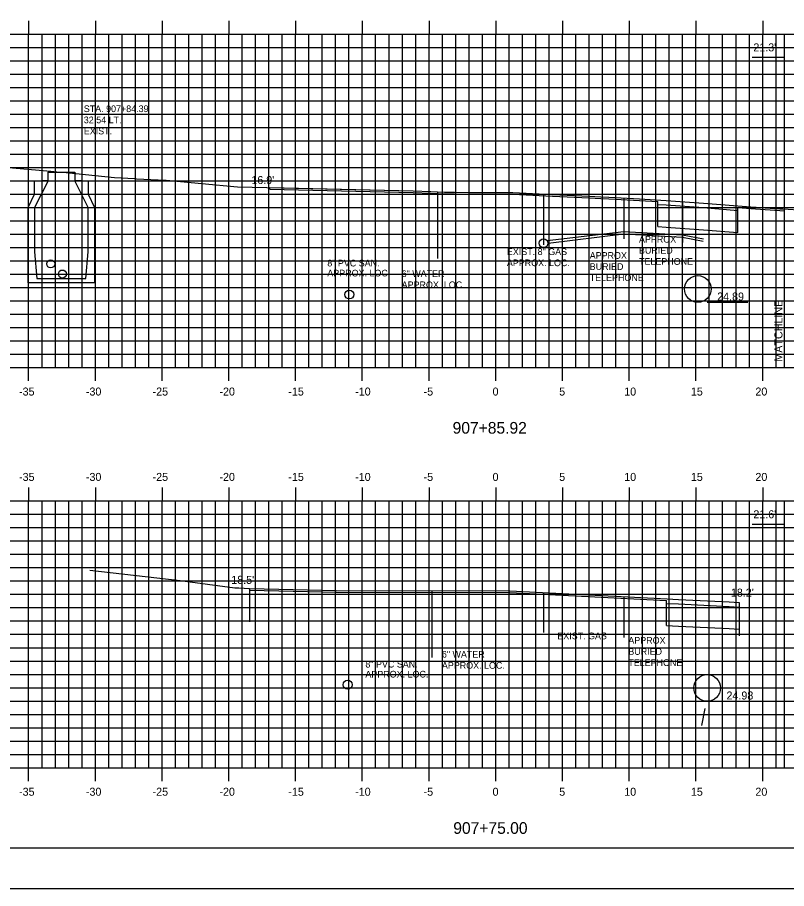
# Model space of a CAD drawing. Extents: x 1026131 to 1026301, y 394697 to 394807.
# Drawn here: x 1026178.5 to 1026236.1, y 394696.5 to 394761.9 of the extents above; entities that cross this region are included whole.
import ezdxf

# ---------------------------------------------------------------- set-up
doc = ezdxf.new("R2010")
doc.units = 0
for name, color, linetype in [('ANNOTATION', 7, 'Continuous'), ('BORDER', 7, 'Continuous'), ('D_Drainage_Culvert', 7, 'Continuous'), ('D_Drainage_Text', 7, 'Continuous'), ('D_Roadway_FinishedGrade', 7, 'Continuous'), ('D_Text_Monospaced', 7, 'Continuous'), ('D_Text_Standard', 7, 'Continuous'), ('H_V ANNOTATION', 7, 'Continuous'), ('MAJOR', 7, 'Continuous'), ('MINOR', 7, 'Continuous'), ('PLOT BOUNDARY', 7, 'Continuous'), ('S_Drainage_CB', 7, 'Continuous'), ('S_Drainage_Invert', 7, 'Continuous'), ('S_Roadway_Centerline', 7, 'Continuous'), ('S_Roadway_Edge_Pavement', 7, 'Continuous'), ('S_Utilities_UG_Gas_Line', 7, 'Continuous'), ('S_Utilities_UG_Sanitary_Sewer', 7, 'Continuous'), ('S_Utilities_UG_Water_Line', 7, 'Continuous')]:
    doc.layers.add(name, color=color, linetype=linetype)

msp = doc.modelspace()

# ---------------------------------------------------------------- linework, layer by layer
at = {"layer": 'ANNOTATION'}
for p, q in [((1026233.564, 394758.868), (1026235.983, 394758.868)), ((1026233.564, 394723.868), (1026235.983, 394723.868)), ((1026229.772, 394708.778), (1026230.039, 394710.054))]:
    msp.add_line(p, q, dxfattribs=at)
at = {"layer": 'BORDER'}
msp.add_line((1026139.345, 394699.607), (1026299.345, 394699.607), dxfattribs=at)
at = {"layer": 'D_Drainage_Culvert'}
for centre in [(1026229.484, 394741.497), (1026230.183, 394711.587)]:
    msp.add_circle(centre, 1, dxfattribs=at)
at = {"layer": 'D_Drainage_Text'}
for points in [[(1026230.179, 394740.519), (1026231.398, 394740.519), (1026233.239, 394740.519)], [(1026230.878, 394710.609), (1026232.097, 394710.609), (1026233.938, 394710.609)]]:
    msp.add_lwpolyline(points, dxfattribs=at)
at = {"layer": 'D_Roadway_FinishedGrade'}
for p, q in [((1026235.983, 394735.607), (1026235.983, 394760.607)), ((1026197.426, 394748.977), (1026197.426, 394749.102)), ((1026226.478, 394746.172), (1026226.478, 394748.047)), ((1026232.478, 394745.725), (1026232.478, 394747.6)), ((1026235.983, 394705.607), (1026235.983, 394725.607)), ((1026227.127, 394716.263), (1026227.127, 394718.139))]:
    msp.add_line(p, q, dxfattribs=at)
for points in [[(1026197.426, 394749.102), (1026207.079, 394748.878), (1026208.153, 394748.844), (1026209.473, 394748.801), (1026210.495, 394748.766), (1026211.246, 394748.752), (1026212.328, 394748.73), (1026215.619, 394748.72), (1026218.593, 394748.568), (1026221.339, 394748.457), (1026222.225, 394748.413), (1026222.825, 394748.372), (1026223.744, 394748.317), (1026225.118, 394748.242), (1026227.118, 394748.139), (1026229.902, 394747.925), (1026233.45, 394747.649), (1026235.983, 394747.488)], [(1026197.426, 394748.977), (1026207.079, 394748.753), (1026208.153, 394748.719), (1026209.473, 394748.676), (1026210.495, 394748.641), (1026211.246, 394748.627), (1026212.328, 394748.605), (1026215.619, 394748.595), (1026218.593, 394748.443), (1026221.339, 394748.332), (1026222.225, 394748.288), (1026222.825, 394748.247), (1026223.744, 394748.192), (1026225.118, 394748.117), (1026226.478, 394748.047)], [(1026226.478, 394747.839), (1026227.118, 394747.806), (1026229.902, 394747.592), (1026232.478, 394747.391)], [(1026232.478, 394747.6), (1026233.45, 394747.524), (1026235.983, 394747.363)], [(1026226.478, 394746.172), (1026227.118, 394746.139), (1026229.902, 394745.925), (1026232.478, 394745.725)], [(1026195.894, 394719.033), (1026198.093, 394718.991), (1026202.376, 394718.903), (1026215.403, 394718.862), (1026227.174, 394718.261), (1026228.046, 394718.226), (1026231.842, 394718.037), (1026232.572, 394717.988)], [(1026195.894, 394718.908), (1026198.093, 394718.866), (1026202.376, 394718.778), (1026215.403, 394718.737), (1026227.127, 394718.139)], [(1026227.127, 394717.93), (1026228.046, 394717.893), (1026231.842, 394717.704), (1026232.572, 394717.655)], [(1026227.127, 394716.263), (1026228.046, 394716.226), (1026231.842, 394716.037), (1026232.572, 394715.988)]]:
    msp.add_lwpolyline(points, dxfattribs=at)
at = {"layer": 'MAJOR'}
for p, q in [((1026179.344, 394761.609), (1026179.344, 394760.607)), ((1026184.344, 394761.609), (1026184.344, 394760.607)), ((1026189.344, 394761.609), (1026189.344, 394760.607)), ((1026194.344, 394761.609), (1026194.344, 394760.607)), ((1026199.344, 394761.609), (1026199.344, 394760.607)), ((1026204.344, 394761.609), (1026204.344, 394760.607)), ((1026209.344, 394761.609), (1026209.344, 394760.607)), ((1026214.344, 394761.609), (1026214.344, 394760.607)), ((1026219.344, 394761.609), (1026219.344, 394760.607)), ((1026224.344, 394761.609), (1026224.344, 394760.607)), ((1026229.344, 394761.609), (1026229.344, 394760.607)), ((1026234.344, 394761.609), (1026234.344, 394760.607)), ((1026144.344, 394760.607), (1026284.344, 394760.607)), ((1026179.344, 394735.607), (1026179.344, 394760.607)), ((1026184.344, 394735.607), (1026184.344, 394760.607)), ((1026189.344, 394735.607), (1026189.344, 394760.607)), ((1026194.344, 394735.607), (1026194.344, 394760.607)), ((1026199.344, 394735.607), (1026199.344, 394760.607)), ((1026204.344, 394735.607), (1026204.344, 394760.607)), ((1026209.344, 394735.607), (1026209.344, 394760.607)), ((1026214.344, 394735.607), (1026214.344, 394760.607)), ((1026219.344, 394735.607), (1026219.344, 394760.607)), ((1026224.344, 394735.607), (1026224.344, 394760.607)), ((1026229.344, 394735.607), (1026229.344, 394760.607)), ((1026234.344, 394735.607), (1026234.344, 394760.607)), ((1026144.344, 394755.607), (1026284.344, 394755.607)), ((1026144.344, 394750.607), (1026284.344, 394750.607)), ((1026144.344, 394745.607), (1026284.344, 394745.607)), ((1026144.344, 394740.607), (1026284.344, 394740.607)), ((1026144.344, 394735.607), (1026284.344, 394735.607)), ((1026179.344, 394734.605), (1026179.344, 394735.607)), ((1026184.344, 394734.605), (1026184.344, 394735.607)), ((1026189.344, 394734.605), (1026189.344, 394735.607)), ((1026194.344, 394734.605), (1026194.344, 394735.607)), ((1026199.344, 394734.605), (1026199.344, 394735.607)), ((1026204.344, 394734.605), (1026204.344, 394735.607)), ((1026209.344, 394734.605), (1026209.344, 394735.607)), ((1026214.344, 394734.605), (1026214.344, 394735.607)), ((1026219.344, 394734.605), (1026219.344, 394735.607)), ((1026224.344, 394734.605), (1026224.344, 394735.607)), ((1026229.344, 394734.605), (1026229.344, 394735.607)), ((1026234.344, 394734.605), (1026234.344, 394735.607)), ((1026179.344, 394726.609), (1026179.344, 394725.607)), ((1026184.344, 394726.609), (1026184.344, 394725.607)), ((1026189.344, 394726.609), (1026189.344, 394725.607)), ((1026194.344, 394726.609), (1026194.344, 394725.607)), ((1026199.344, 394726.609), (1026199.344, 394725.607)), ((1026204.344, 394726.609), (1026204.344, 394725.607)), ((1026209.344, 394726.609), (1026209.344, 394725.607)), ((1026214.344, 394726.609), (1026214.344, 394725.607)), ((1026219.344, 394726.609), (1026219.344, 394725.607)), ((1026224.344, 394726.609), (1026224.344, 394725.607)), ((1026229.344, 394726.609), (1026229.344, 394725.607)), ((1026234.344, 394726.609), (1026234.344, 394725.607)), ((1026144.344, 394725.607), (1026284.344, 394725.607)), ((1026179.344, 394705.607), (1026179.344, 394725.607)), ((1026184.344, 394705.607), (1026184.344, 394725.607)), ((1026189.344, 394705.607), (1026189.344, 394725.607)), ((1026194.344, 394705.607), (1026194.344, 394725.607)), ((1026199.344, 394705.607), (1026199.344, 394725.607)), ((1026204.344, 394705.607), (1026204.344, 394725.607)), ((1026209.344, 394705.607), (1026209.344, 394725.607)), ((1026214.344, 394705.607), (1026214.344, 394725.607)), ((1026219.344, 394705.607), (1026219.344, 394725.607)), ((1026224.344, 394705.607), (1026224.344, 394725.607)), ((1026229.344, 394705.607), (1026229.344, 394725.607)), ((1026234.344, 394705.607), (1026234.344, 394725.607)), ((1026144.344, 394720.607), (1026284.344, 394720.607)), ((1026144.344, 394715.607), (1026284.344, 394715.607)), ((1026144.344, 394710.607), (1026284.344, 394710.607)), ((1026144.344, 394705.607), (1026284.344, 394705.607)), ((1026179.344, 394704.605), (1026179.344, 394705.607)), ((1026184.344, 394704.605), (1026184.344, 394705.607)), ((1026189.344, 394704.605), (1026189.344, 394705.607)), ((1026194.344, 394704.605), (1026194.344, 394705.607)), ((1026199.344, 394704.605), (1026199.344, 394705.607)), ((1026204.344, 394704.605), (1026204.344, 394705.607)), ((1026209.344, 394704.605), (1026209.344, 394705.607)), ((1026214.344, 394704.605), (1026214.344, 394705.607)), ((1026219.344, 394704.605), (1026219.344, 394705.607)), ((1026224.344, 394704.605), (1026224.344, 394705.607)), ((1026229.344, 394704.605), (1026229.344, 394705.607)), ((1026234.344, 394704.605), (1026234.344, 394705.607))]:
    msp.add_line(p, q, dxfattribs=at)
at = {"layer": 'MINOR'}
for p, q in [((1026180.344, 394735.607), (1026180.344, 394760.607)), ((1026181.344, 394735.607), (1026181.344, 394760.607)), ((1026182.344, 394735.607), (1026182.344, 394760.607)), ((1026183.344, 394735.607), (1026183.344, 394760.607)), ((1026185.344, 394735.607), (1026185.344, 394760.607)), ((1026186.344, 394735.607), (1026186.344, 394760.607)), ((1026187.344, 394735.607), (1026187.344, 394760.607)), ((1026188.344, 394735.607), (1026188.344, 394760.607)), ((1026190.344, 394735.607), (1026190.344, 394760.607)), ((1026191.344, 394735.607), (1026191.344, 394760.607)), ((1026192.344, 394735.607), (1026192.344, 394760.607)), ((1026193.344, 394735.607), (1026193.344, 394760.607)), ((1026195.344, 394735.607), (1026195.344, 394760.607)), ((1026196.344, 394735.607), (1026196.344, 394760.607)), ((1026197.344, 394735.607), (1026197.344, 394760.607)), ((1026198.344, 394735.607), (1026198.344, 394760.607)), ((1026200.344, 394735.607), (1026200.344, 394760.607)), ((1026201.344, 394735.607), (1026201.344, 394760.607)), ((1026202.344, 394735.607), (1026202.344, 394760.607)), ((1026203.344, 394735.607), (1026203.344, 394760.607)), ((1026205.344, 394735.607), (1026205.344, 394760.607)), ((1026206.344, 394735.607), (1026206.344, 394760.607)), ((1026207.344, 394735.607), (1026207.344, 394760.607)), ((1026208.344, 394735.607), (1026208.344, 394760.607)), ((1026210.344, 394735.607), (1026210.344, 394760.607)), ((1026211.344, 394735.607), (1026211.344, 394760.607)), ((1026212.344, 394735.607), (1026212.344, 394760.607)), ((1026213.344, 394735.607), (1026213.344, 394760.607)), ((1026215.344, 394735.607), (1026215.344, 394760.607)), ((1026216.344, 394735.607), (1026216.344, 394760.607)), ((1026217.344, 394735.607), (1026217.344, 394760.607)), ((1026218.344, 394735.607), (1026218.344, 394760.607)), ((1026220.344, 394735.607), (1026220.344, 394760.607)), ((1026221.344, 394735.607), (1026221.344, 394760.607)), ((1026222.344, 394735.607), (1026222.344, 394760.607)), ((1026223.344, 394735.607), (1026223.344, 394760.607)), ((1026225.344, 394735.607), (1026225.344, 394760.607)), ((1026226.344, 394735.607), (1026226.344, 394760.607)), ((1026227.344, 394735.607), (1026227.344, 394760.607)), ((1026228.344, 394735.607), (1026228.344, 394760.607)), ((1026230.344, 394735.607), (1026230.344, 394760.607)), ((1026231.344, 394735.607), (1026231.344, 394760.607)), ((1026232.344, 394735.607), (1026232.344, 394760.607)), ((1026233.344, 394735.607), (1026233.344, 394760.607)), ((1026235.344, 394735.607), (1026235.344, 394760.607)), ((1026144.344, 394759.607), (1026284.344, 394759.607)), ((1026144.344, 394758.607), (1026284.344, 394758.607)), ((1026144.344, 394757.607), (1026284.344, 394757.607)), ((1026144.344, 394756.607), (1026284.344, 394756.607)), ((1026144.344, 394754.607), (1026284.344, 394754.607)), ((1026144.344, 394753.607), (1026284.344, 394753.607)), ((1026144.344, 394752.607), (1026284.344, 394752.607)), ((1026144.344, 394751.607), (1026284.344, 394751.607)), ((1026144.344, 394749.607), (1026284.344, 394749.607)), ((1026144.344, 394748.607), (1026284.344, 394748.607)), ((1026144.344, 394747.607), (1026284.344, 394747.607)), ((1026144.344, 394746.607), (1026284.344, 394746.607)), ((1026144.344, 394744.607), (1026284.344, 394744.607)), ((1026144.344, 394743.607), (1026284.344, 394743.607)), ((1026144.344, 394742.607), (1026284.344, 394742.607)), ((1026144.344, 394741.607), (1026284.344, 394741.607)), ((1026144.344, 394739.607), (1026284.344, 394739.607)), ((1026144.344, 394738.607), (1026284.344, 394738.607)), ((1026144.344, 394737.607), (1026284.344, 394737.607)), ((1026144.344, 394736.607), (1026284.344, 394736.607)), ((1026180.344, 394705.607), (1026180.344, 394725.607)), ((1026181.344, 394705.607), (1026181.344, 394725.607)), ((1026182.344, 394705.607), (1026182.344, 394725.607)), ((1026183.344, 394705.607), (1026183.344, 394725.607)), ((1026185.344, 394705.607), (1026185.344, 394725.607)), ((1026186.344, 394705.607), (1026186.344, 394725.607)), ((1026187.344, 394705.607), (1026187.344, 394725.607)), ((1026188.344, 394705.607), (1026188.344, 394725.607)), ((1026190.344, 394705.607), (1026190.344, 394725.607)), ((1026191.344, 394705.607), (1026191.344, 394725.607)), ((1026192.344, 394705.607), (1026192.344, 394725.607)), ((1026193.344, 394705.607), (1026193.344, 394725.607)), ((1026195.344, 394705.607), (1026195.344, 394725.607)), ((1026196.344, 394705.607), (1026196.344, 394725.607)), ((1026197.344, 394705.607), (1026197.344, 394725.607)), ((1026198.344, 394705.607), (1026198.344, 394725.607)), ((1026200.344, 394705.607), (1026200.344, 394725.607)), ((1026201.344, 394705.607), (1026201.344, 394725.607)), ((1026202.344, 394705.607), (1026202.344, 394725.607)), ((1026203.344, 394705.607), (1026203.344, 394725.607)), ((1026205.344, 394705.607), (1026205.344, 394725.607)), ((1026206.344, 394705.607), (1026206.344, 394725.607)), ((1026207.344, 394705.607), (1026207.344, 394725.607)), ((1026208.344, 394705.607), (1026208.344, 394725.607)), ((1026210.344, 394705.607), (1026210.344, 394725.607)), ((1026211.344, 394705.607), (1026211.344, 394725.607)), ((1026212.344, 394705.607), (1026212.344, 394725.607)), ((1026213.344, 394705.607), (1026213.344, 394725.607)), ((1026215.344, 394705.607), (1026215.344, 394725.607)), ((1026216.344, 394705.607), (1026216.344, 394725.607)), ((1026217.344, 394705.607), (1026217.344, 394725.607)), ((1026218.344, 394705.607), (1026218.344, 394725.607)), ((1026220.344, 394705.607), (1026220.344, 394725.607)), ((1026221.344, 394705.607), (1026221.344, 394725.607)), ((1026222.344, 394705.607), (1026222.344, 394725.607)), ((1026223.344, 394705.607), (1026223.344, 394725.607)), ((1026225.344, 394705.607), (1026225.344, 394725.607)), ((1026226.344, 394705.607), (1026226.344, 394725.607)), ((1026227.344, 394705.607), (1026227.344, 394725.607)), ((1026228.344, 394705.607), (1026228.344, 394725.607)), ((1026230.344, 394705.607), (1026230.344, 394725.607)), ((1026231.344, 394705.607), (1026231.344, 394725.607)), ((1026232.344, 394705.607), (1026232.344, 394725.607)), ((1026233.344, 394705.607), (1026233.344, 394725.607)), ((1026235.344, 394705.607), (1026235.344, 394725.607)), ((1026144.344, 394724.607), (1026284.344, 394724.607)), ((1026144.344, 394723.607), (1026284.344, 394723.607)), ((1026144.344, 394722.607), (1026284.344, 394722.607)), ((1026144.344, 394721.607), (1026284.344, 394721.607)), ((1026144.344, 394719.607), (1026284.344, 394719.607)), ((1026144.344, 394718.607), (1026284.344, 394718.607)), ((1026144.344, 394717.607), (1026284.344, 394717.607)), ((1026144.344, 394716.607), (1026284.344, 394716.607)), ((1026144.344, 394714.607), (1026284.344, 394714.607)), ((1026144.344, 394713.607), (1026284.344, 394713.607)), ((1026144.344, 394712.607), (1026284.344, 394712.607)), ((1026144.344, 394711.607), (1026284.344, 394711.607)), ((1026144.344, 394709.607), (1026284.344, 394709.607)), ((1026144.344, 394708.607), (1026284.344, 394708.607)), ((1026144.344, 394707.607), (1026284.344, 394707.607)), ((1026144.344, 394706.607), (1026284.344, 394706.607))]:
    msp.add_line(p, q, dxfattribs=at)
at = {"layer": 'PLOT BOUNDARY'}
msp.add_lwpolyline([(1026131.251, 394696.548), (1026301.251, 394696.548), (1026301.251, 394806.548), (1026131.251, 394806.548)], close=True, dxfattribs=at)
at = {"layer": 'S_Drainage_CB'}
for p, q in [((1026179.791, 394748.609), (1026179.791, 394749.593)), ((1026179.791, 394749.593), (1026180.808, 394749.593)), ((1026180.808, 394749.593), (1026179.791, 394747.592)), ((1026182.809, 394749.593), (1026183.794, 394749.593)), ((1026183.794, 394747.592), (1026182.809, 394749.593)), ((1026183.794, 394749.593), (1026183.794, 394748.609)), ((1026179.299, 394747.592), (1026179.791, 394748.609)), ((1026183.794, 394748.609), (1026184.286, 394747.592)), ((1026179.299, 394741.949), (1026179.299, 394747.592)), ((1026179.791, 394747.592), (1026179.791, 394744.278)), ((1026183.794, 394744.278), (1026183.794, 394747.592)), ((1026184.286, 394747.592), (1026184.286, 394741.949)), ((1026179.791, 394744.278), (1026179.955, 394742.277)), ((1026183.63, 394742.277), (1026183.794, 394744.278)), ((1026179.955, 394742.277), (1026183.63, 394742.277)), ((1026184.286, 394741.949), (1026179.299, 394741.949))]:
    msp.add_line(p, q, dxfattribs=at)
msp.add_lwpolyline([(1026180.316, 394749.635), (1026180.808, 394749.635), (1026180.808, 394750.258), (1026182.809, 394750.258), (1026182.809, 394749.635), (1026183.301, 394749.635)], dxfattribs=at)
at = {"layer": 'S_Drainage_Invert'}
for centre in [(1026180.996, 394743.38), (1026181.872, 394742.619)]:
    msp.add_circle(centre, 0.3, dxfattribs=at)
at = {"layer": 'S_Roadway_Centerline'}
for points in [[(1026164.577, 394751.744), (1026181.002, 394750.326), (1026181.69, 394750.257), (1026182.149, 394750.228), (1026182.162, 394750.227), (1026185.786, 394749.86), (1026187.271, 394749.767), (1026187.434, 394749.754), (1026189.053, 394749.679), (1026189.652, 394749.641), (1026194.984, 394749.158), (1026207.079, 394748.878), (1026208.153, 394748.844), (1026209.473, 394748.801), (1026210.495, 394748.766), (1026211.246, 394748.752), (1026212.328, 394748.73), (1026215.619, 394748.72), (1026218.593, 394748.568), (1026221.339, 394748.457), (1026222.225, 394748.413), (1026222.825, 394748.372), (1026223.744, 394748.317), (1026225.118, 394748.242), (1026227.118, 394748.139), (1026229.902, 394747.925), (1026233.45, 394747.649), (1026239.83, 394747.244)], [(1026183.923, 394720.429), (1026190.689, 394719.645), (1026194.804, 394719.102), (1026195.091, 394719.09), (1026195.48, 394719.069), (1026195.846, 394719.033), (1026195.894, 394719.033), (1026198.093, 394718.991), (1026202.376, 394718.903), (1026215.403, 394718.862), (1026227.174, 394718.261), (1026228.046, 394718.226), (1026231.842, 394718.037), (1026232.572, 394717.988)]]:
    msp.add_lwpolyline(points, dxfattribs=at)
at = {"layer": 'S_Roadway_Edge_Pavement'}
for p, q in [((1026195.894, 394719.033), (1026195.894, 394716.533)), ((1026232.572, 394717.988), (1026232.572, 394715.488))]:
    msp.add_line(p, q, dxfattribs=at)
at = {"layer": 'S_Utilities_UG_Gas_Line'}
for p, q in [((1026217.925, 394748.602), (1026217.925, 394745.602)), ((1026217.925, 394745.607), (1026217.925, 394744.801)), ((1026217.914, 394718.734), (1026217.914, 394715.734))]:
    msp.add_line(p, q, dxfattribs=at)
for points in [[(1026218.197, 394745.121), (1026223.944, 394745.8), (1026228.344, 394745.545), (1026229.908, 394745.247)], [(1026218.258, 394744.928), (1026223.947, 394745.633), (1026228.324, 394745.379), (1026229.876, 394745.083)]]:
    msp.add_lwpolyline(points, dxfattribs=at)
msp.add_circle((1026217.925, 394744.928), 0.333, dxfattribs=at)
at = {"layer": 'S_Utilities_UG_Sanitary_Sewer'}
for centre in [(1026203.367, 394741.08), (1026203.245, 394711.83)]:
    msp.add_circle(centre, 0.333, dxfattribs=at)
at = {"layer": 'S_Utilities_UG_Water_Line'}
for p, q in [((1026209.98, 394748.784), (1026209.98, 394743.784)), ((1026223.944, 394748.306), (1026223.944, 394745.253)), ((1026228.344, 394748.045), (1026228.344, 394744.992)), ((1026209.56, 394718.88), (1026209.56, 394713.88)), ((1026223.944, 394718.426), (1026223.944, 394715.373))]:
    msp.add_line(p, q, dxfattribs=at)

# ---------------------------------------------------------------- texts
at = {"layer": 'ANNOTATION'}
for s, p in [("21.3'", (1026233.644, 394759.307)), ("21.6'", (1026233.644, 394724.307))]:
    msp.add_text(s, height=0.6, dxfattribs=at).set_placement(p)
msp.add_text('MATCHLINE', height=0.6, rotation=90, dxfattribs=at).set_placement((1026235.824, 394736.048))
at = {"layer": 'D_Drainage_Text'}
for s, p in [('24.89', (1026230.933, 394740.632)), ('24.98', (1026231.632, 394710.722))]:
    msp.add_text(s, height=0.6, dxfattribs=at).set_placement(p)
at = {"layer": 'D_Text_Monospaced'}
for s, height, p in [('STA. 907+84.39', 0.49998, (1026183.475, 394754.756)), ('32.54 LT.', 0.5, (1026183.475, 394753.922)), ('EXIST. ', 0.5, (1026183.475, 394753.082)), ('APPROX', 0.5, (1026225.075, 394744.973)), ('EXIST. 8" GAS', 0.49998, (1026215.176, 394744.04)), ('APPROX', 0.5, (1026221.382, 394743.758)), ('BURIED ', 0.5, (1026225.075, 394744.14)), ('8" PVC SAN.', 0.49998, (1026201.722, 394743.186)), ('APPROX. LOC.', 0.49998, (1026215.176, 394743.207)), ('BURIED ', 0.5, (1026221.382, 394742.925)), ('TELEPHONE', 0.5, (1026225.075, 394743.307)), ('APPROX. LOC.', 0.49998, (1026201.722, 394742.436)), ('6" WATER', 0.5, (1026207.292, 394742.393)), ('TELEPHONE', 0.5, (1026221.382, 394742.091)), ('APPROX. LOC.', 0.49998, (1026207.292, 394741.56)), ('EXIST. GAS', 0.5, (1026218.954, 394715.239)), ('APPROX', 0.5, (1026224.276, 394714.905)), ('6" WATER', 0.5, (1026210.308, 394713.86)), ('BURIED ', 0.5, (1026224.276, 394714.072)), ('8" PVC SAN.', 0.49998, (1026204.574, 394713.12)), ('APPROX. LOC.', 0.49998, (1026210.308, 394713.027)), ('TELEPHONE', 0.5, (1026224.276, 394713.239)), ('APPROX. LOC.', 0.49998, (1026204.574, 394712.37))]:
    msp.add_text(s, height=height, dxfattribs=at).set_placement(p)
at = {"layer": 'D_Text_Standard'}
for s, p in [("-16.9'", (1026195.764, 394749.362)), ("-18.5'", (1026194.258, 394719.392)), ("18.2'", (1026231.962, 394718.434))]:
    msp.add_text(s, height=0.6, dxfattribs=at).set_placement(p)
at = {"layer": 'H_V ANNOTATION'}
for s, height, p in [('-35', 0.6, (1026178.624, 394733.507)), ('-30', 0.6, (1026183.632, 394733.507)), ('-25', 0.6, (1026188.63, 394733.507)), ('-20', 0.6, (1026193.638, 394733.507)), ('-15', 0.6, (1026198.801, 394733.507)), ('-10', 0.6, (1026203.809, 394733.507)), ('-5', 0.6, (1026208.935, 394733.507)), ('0', 0.6, (1026214.103, 394733.507)), ('5', 0.6, (1026219.095, 394733.507)), ('10', 0.6, (1026223.97, 394733.507)), ('15', 0.6, (1026228.962, 394733.507)), ('20', 0.6, (1026233.798, 394733.507)), ('907+85.92', 0.875, (1026211.11, 394730.65)), ('-35', 0.6, (1026178.624, 394727.107)), ('-30', 0.6, (1026183.632, 394727.107)), ('-25', 0.6, (1026188.63, 394727.107)), ('-20', 0.6, (1026193.638, 394727.107)), ('-15', 0.6, (1026198.801, 394727.107)), ('-10', 0.6, (1026203.809, 394727.107)), ('-5', 0.6, (1026208.935, 394727.107)), ('0', 0.6, (1026214.103, 394727.107)), ('5', 0.6, (1026219.095, 394727.107)), ('10', 0.6, (1026223.97, 394727.107)), ('15', 0.6, (1026228.962, 394727.107)), ('20', 0.6, (1026233.798, 394727.107)), ('-35', 0.6, (1026178.624, 394703.507)), ('-30', 0.6, (1026183.632, 394703.507)), ('-25', 0.6, (1026188.63, 394703.507)), ('-20', 0.6, (1026193.638, 394703.507)), ('-15', 0.6, (1026198.801, 394703.507)), ('-10', 0.6, (1026203.809, 394703.507)), ('-5', 0.6, (1026208.935, 394703.507)), ('0', 0.6, (1026214.103, 394703.507)), ('5', 0.6, (1026219.095, 394703.507)), ('10', 0.6, (1026223.97, 394703.507)), ('15', 0.6, (1026228.962, 394703.507)), ('20', 0.6, (1026233.798, 394703.507)), ('907+75.00', 0.875, (1026211.16, 394700.65))]:
    msp.add_text(s, height=height, dxfattribs=at).set_placement(p)
at = {"layer": 'S_Roadway_Centerline'}
for s, p in [('C', (1026215.614, 394748.72)), ('L', (1026215.619, 394748.712)), ('C', (1026215.398, 394718.862)), ('L', (1026215.403, 394718.855))]:
    msp.add_text(s, height=0.0146, dxfattribs=at).set_placement(p)

doc.saveas('drawing.dxf')
